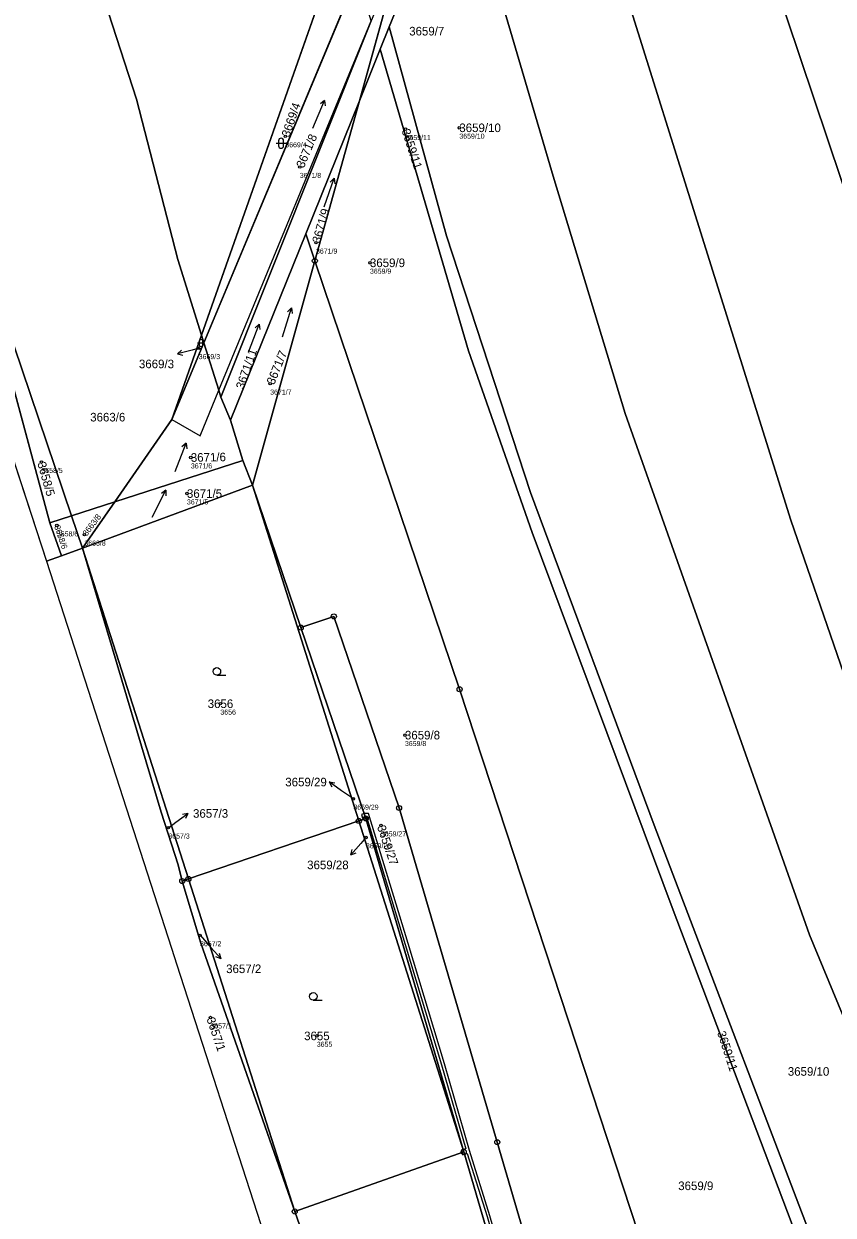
# Model space of a CAD drawing. Extents: x -761174 to -757114, y -1063806 to -1059397.
# Drawn here: x -760564.3 to -760404, y -1062680.5 to -1062444.5 of the extents above; entities that cross this region are included whole.
import ezdxf

# ---------------------------------------------------------------- set-up
doc = ezdxf.new("R2010")
doc.units = 0
for name, color, linetype in [('Definiční body', 7, 'Continuous'), ('Hranice parcel', 7, 'Continuous'), ('Parcelní čísla', 7, 'Continuous'), ('Polygon ku', 7, 'Continuous'), ('Polygon parcely', 7, 'Continuous'), ('Pop  PČ popisy', 7, 'Continuous'), ('Vnitřní kresba', 7, 'Continuous'), ('Věcná břemena k části', 7, 'Continuous'), ('Značky bodu BP', 7, 'Continuous'), ('Značky kultur', 7, 'Continuous')]:
    doc.layers.add(name, color=color, linetype=linetype)

msp = doc.modelspace()

# ---------------------------------------------------------------- linework, layer by layer
at = {"layer": 'Definiční body'}
for centre in [(-760512.49, -1062466.82), (-760488.67, -1062465.4), (-760478.03, -1062465.12), (-760509.62, -1062472.89), (-760506.41, -1062487.88), (-760495.73, -1062491.86), (-760529.63, -1062508.78), (-760515.48, -1062515.81), (-760531.19, -1062530.43), (-760560.78, -1062531.33), (-760531.96, -1062537.56), (-760557.71, -1062543.88), (-760552.27, -1062545.71), (-760525.34, -1062579.19), (-760488.8, -1062585.41), (-760499.01, -1062598.02), (-760535.64, -1062603.74), (-760493.55, -1062603.31), (-760496.52, -1062605.68), (-760529.37, -1062625.06), (-760527.31, -1062641.35), (-760506.25, -1062644.98)]:
    msp.add_circle(centre, 0.25, dxfattribs=at)
at = {"layer": 'Hranice parcel'}
for p, q in [((-760529.07, -1062506.18), (-760500.79, -1062425.75)), ((-760497.82, -1062459.77), (-760489.47, -1062429.76)), ((-760528.6, -1062507.69), (-760498.2, -1062434.94)), ((-760525.22, -1062518.46), (-760495.48, -1062443.91)), ((-760493.69, -1062449.54), (-760491.89, -1062445.1)), ((-760497.82, -1062459.77), (-760493.69, -1062449.54)), ((-760591.44, -1062454.1), (-760559.78, -1062550.95)), ((-760497.82, -1062459.77), (-760508.45, -1062486.1)), ((-760506.64, -1062491.46), (-760497.82, -1062459.77)), ((-760559.12, -1062543.33), (-760577.66, -1062474.56)), ((-760554.81, -1062541.95), (-760577.66, -1062474.56)), ((-760508.45, -1062486.1), (-760523.34, -1062523)), ((-760506.64, -1062491.46), (-760508.45, -1062486.1)), ((-760519.01, -1062535.92), (-760506.64, -1062491.46)), ((-760534.95, -1062522.89), (-760529.07, -1062506.18)), ((-760528.6, -1062507.69), (-760529.07, -1062506.18)), ((-760534.95, -1062522.89), (-760528.6, -1062507.69)), ((-760523.34, -1062523), (-760525.22, -1062518.46)), ((-760546.26, -1062539.2), (-760534.95, -1062522.89)), ((-760520.92, -1062531.04), (-760523.34, -1062523)), ((-760520.92, -1062531.04), (-760546.26, -1062539.2)), ((-760519.01, -1062535.92), (-760520.92, -1062531.04)), ((-760519.01, -1062535.92), (-760552.63, -1062548.39)), ((-760519.01, -1062535.92), (-760509.42, -1062564.12)), ((-760497.93, -1062602.4), (-760519.01, -1062535.92)), ((-760554.81, -1062541.95), (-760546.26, -1062539.2)), ((-760552.63, -1062548.39), (-760546.26, -1062539.2)), ((-760559.12, -1062543.33), (-760554.81, -1062541.95)), ((-760552.63, -1062548.39), (-760554.81, -1062541.95)), ((-760556.8, -1062549.88), (-760559.12, -1062543.33)), ((-760556.8, -1062549.88), (-760552.63, -1062548.39)), ((-760537.09, -1062600.69), (-760552.63, -1062548.39)), ((-760552.63, -1062548.39), (-760531.68, -1062613.9)), ((-760559.78, -1062550.95), (-760556.8, -1062549.88)), ((-760559.78, -1062550.95), (-760535.03, -1062627.6)), ((-760509.42, -1062564.12), (-760496.56, -1062601.93)), ((-760497.93, -1062602.4), (-760531.68, -1062613.9)), ((-760496.56, -1062601.93), (-760497.93, -1062602.4)), ((-760477.15, -1062667.96), (-760497.93, -1062602.4)), ((-760496.56, -1062601.93), (-760477.15, -1062667.96)), ((-760531.68, -1062613.9), (-760532.88, -1062614.31)), ((-760529.19, -1062626.62), (-760532.88, -1062614.31)), ((-760531.68, -1062613.9), (-760510.62, -1062679.76)), ((-760510.62, -1062679.76), (-760529.19, -1062626.62)), ((-760535.03, -1062627.6), (-760533.95, -1062630.93)), ((-760477.15, -1062667.96), (-760510.62, -1062679.76)), ((-760456.61, -1062738.15), (-760477.15, -1062667.96)), ((-760510.62, -1062679.76), (-760485.29, -1062752.31))]:
    msp.add_line(p, q, dxfattribs=at)
for points in [[(-760359.03, -1062598.65), (-760377.94, -1062548.27), (-760415.94, -1062435.02), (-760457.73, -1062294.15), (-760467.66, -1062267.71)], [(-760378.94, -1062635.52), (-760392.71, -1062599.89), (-760412.37, -1062542.84), (-760446.07, -1062435.29), (-760476.28, -1062329.05)], [(-760580.16, -1062341.72), (-760541.95, -1062459.45), (-760533.78, -1062491.19), (-760529.07, -1062506.18)], [(-760390.99, -1062667.67), (-760408.72, -1062624.98), (-760445.22, -1062521.7), (-760459.47, -1062474.68), (-760482.65, -1062395.66)], [(-760491.89, -1062445.1), (-760489.82, -1062439.96), (-760489.47, -1062429.76)], [(-760491.89, -1062445.1), (-760480.56, -1062486.5), (-760463.94, -1062537.36), (-760439.48, -1062603.21), (-760404.16, -1062695.94)], [(-760406.03, -1062698.38), (-760435.9, -1062619.55), (-760463.6, -1062545.28), (-760476.2, -1062509.31), (-760493.69, -1062449.54)], [(-760430.23, -1062721.73), (-760477.98, -1062576.32), (-760506.64, -1062491.46)], [(-760525.22, -1062518.46), (-760525.65, -1062517.09), (-760528.6, -1062507.69)], [(-760509.42, -1062564.12), (-760502.88, -1062561.89), (-760489.97, -1062599.84), (-760470.52, -1062666.02), (-760450.33, -1062735.04)], [(-760532.88, -1062614.31), (-760533.73, -1062611.1), (-760537.09, -1062600.69)], [(-760533.95, -1062630.93), (-760517.41, -1062682.16), (-760512.39, -1062694.98)]]:
    msp.add_lwpolyline(points, dxfattribs=at)
at = {"layer": 'Polygon ku'}
msp.add_lwpolyline([(-760641.69, -1062278.11), (-760615.05, -1062378.32), (-760614.77, -1062379.37), (-760614.04, -1062381.71), (-760591.44, -1062454.1), (-760559.78, -1062550.95), (-760535.03, -1062627.6), (-760533.95, -1062630.93), (-760517.41, -1062682.16), (-760512.39, -1062694.98), (-760503.17, -1062718.49), (-760492.21, -1062746.48), (-760517.18, -1062759.09), (-760525.26, -1062765.8), (-760535.26, -1062774.1), (-760557.5, -1062792.57), (-760589.26, -1062821.58), (-760637.28, -1062871.13)], dxfattribs=at)
at = {"layer": 'Polygon parcely'}
for points in [[(-760533.78, -1062491.19), (-760529.07, -1062506.18), (-760500.79, -1062425.75), (-760575.71, -1062179.08), (-760592.88, -1062117.85), (-760608.98, -1062059.6), (-760619.86, -1062023.13), (-760635.57, -1061977.23), (-760679.98, -1061865.8), (-760701.9, -1061821.27), (-760704.64, -1061824.79), (-760730.48, -1061860.52), (-760714.97, -1061897.09), (-760670.71, -1062020.74), (-760625.06, -1062187.5), (-760580.16, -1062341.72), (-760541.95, -1062459.45)], [(-760369.55, -1062448.69), (-760407.18, -1062305.67), (-760440.79, -1062189.54), (-760467.28, -1062265.76), (-760467.66, -1062267.71), (-760457.73, -1062294.15), (-760415.94, -1062435.02), (-760377.94, -1062548.27), (-760359.03, -1062598.65), (-760351.17, -1062587.7), (-760338.23, -1062572.36), (-760330.52, -1062565.65)], [(-760377.94, -1062548.27), (-760415.94, -1062435.02), (-760457.73, -1062294.15), (-760467.66, -1062267.71), (-760473.09, -1062295.7), (-760475.17, -1062317.47), (-760476.28, -1062329.05), (-760446.07, -1062435.29), (-760412.37, -1062542.84), (-760392.71, -1062599.89), (-760378.94, -1062635.52), (-760375.77, -1062627.04), (-760366.24, -1062608.68), (-760359.03, -1062598.65)], [(-760412.37, -1062542.84), (-760446.07, -1062435.29), (-760476.28, -1062329.05), (-760478.1, -1062348.09), (-760482.65, -1062395.66), (-760459.47, -1062474.68), (-760445.22, -1062521.7), (-760408.72, -1062624.98), (-760390.99, -1062667.67), (-760388.52, -1062661.21), (-760378.94, -1062635.52), (-760392.71, -1062599.89)], [(-760554.81, -1062541.95), (-760546.26, -1062539.2), (-760534.95, -1062522.89), (-760529.07, -1062506.18), (-760533.78, -1062491.19), (-760541.95, -1062459.45), (-760580.16, -1062341.72), (-760618.87, -1062350.37), (-760610.19, -1062377.86), (-760588.97, -1062441.1), (-760585.34, -1062441.77), (-760577.66, -1062474.56)], [(-760591.44, -1062454.1), (-760559.78, -1062550.95), (-760556.8, -1062549.88), (-760559.12, -1062543.33), (-760577.66, -1062474.56), (-760585.11, -1062452.59), (-760588.97, -1062441.1), (-760592.44, -1062440.45), (-760606.15, -1062400.62), (-760611.88, -1062381.5), (-760614.04, -1062381.71)], [(-760491.89, -1062445.1), (-760480.56, -1062486.5), (-760463.94, -1062537.36), (-760439.48, -1062603.21), (-760404.16, -1062695.94), (-760399.41, -1062689.74), (-760390.99, -1062667.67), (-760408.72, -1062624.98), (-760445.22, -1062521.7), (-760459.47, -1062474.68), (-760482.65, -1062395.66), (-760484.23, -1062412.14), (-760489.1, -1062428.43), (-760489.47, -1062429.76), (-760489.82, -1062439.96)], [(-760489.47, -1062429.76), (-760488.84, -1062411.43), (-760492.38, -1062420.57), (-760493.6, -1062439.33), (-760495.48, -1062443.91), (-760525.22, -1062518.46), (-760523.34, -1062523), (-760508.45, -1062486.1), (-760497.82, -1062459.77)], [(-760498.2, -1062434.94), (-760500.79, -1062425.75), (-760529.07, -1062506.18), (-760528.6, -1062507.69)], [(-760491.89, -1062445.1), (-760489.82, -1062439.96), (-760489.47, -1062429.76), (-760497.82, -1062459.77), (-760493.69, -1062449.54)], [(-760495.48, -1062443.91), (-760498.2, -1062434.94), (-760528.6, -1062507.69), (-760525.65, -1062517.09), (-760525.22, -1062518.46)], [(-760406.03, -1062698.38), (-760404.16, -1062695.94), (-760439.48, -1062603.21), (-760463.94, -1062537.36), (-760480.56, -1062486.5), (-760491.89, -1062445.1), (-760493.69, -1062449.54), (-760476.2, -1062509.31), (-760463.6, -1062545.28), (-760435.9, -1062619.55)], [(-760463.6, -1062545.28), (-760476.2, -1062509.31), (-760493.69, -1062449.54), (-760497.82, -1062459.77), (-760506.64, -1062491.46), (-760477.98, -1062576.32), (-760430.23, -1062721.73), (-760414.66, -1062709.65), (-760406.03, -1062698.38), (-760435.9, -1062619.55)], [(-760497.82, -1062459.77), (-760508.45, -1062486.1), (-760506.64, -1062491.46)], [(-760577.66, -1062474.56), (-760559.12, -1062543.33), (-760554.81, -1062541.95)], [(-760508.45, -1062486.1), (-760523.34, -1062523), (-760520.92, -1062531.04), (-760519.01, -1062535.92), (-760506.64, -1062491.46)], [(-760470.52, -1062666.02), (-760450.33, -1062735.04), (-760445.89, -1062732.85), (-760431.46, -1062722.68), (-760430.23, -1062721.73), (-760477.98, -1062576.32), (-760506.64, -1062491.46), (-760519.01, -1062535.92), (-760509.42, -1062564.12), (-760502.88, -1062561.89), (-760489.97, -1062599.84)], [(-760528.6, -1062507.69), (-760529.07, -1062506.18), (-760534.95, -1062522.89)], [(-760520.92, -1062531.04), (-760523.34, -1062523), (-760525.22, -1062518.46), (-760525.65, -1062517.09), (-760528.6, -1062507.69), (-760534.95, -1062522.89), (-760546.26, -1062539.2)], [(-760546.26, -1062539.2), (-760552.63, -1062548.39), (-760519.01, -1062535.92), (-760520.92, -1062531.04)], [(-760497.93, -1062602.4), (-760519.01, -1062535.92), (-760552.63, -1062548.39), (-760531.68, -1062613.9)], [(-760519.01, -1062535.92), (-760497.93, -1062602.4), (-760496.56, -1062601.93), (-760509.42, -1062564.12)], [(-760546.26, -1062539.2), (-760554.81, -1062541.95), (-760552.63, -1062548.39)], [(-760552.63, -1062548.39), (-760554.81, -1062541.95), (-760559.12, -1062543.33), (-760556.8, -1062549.88)], [(-760503.17, -1062718.49), (-760492.21, -1062746.48), (-760489.57, -1062753.22), (-760485.29, -1062752.31), (-760510.62, -1062679.76), (-760529.19, -1062626.62), (-760532.88, -1062614.31), (-760533.73, -1062611.1), (-760537.09, -1062600.69), (-760552.63, -1062548.39), (-760556.8, -1062549.88), (-760559.78, -1062550.95), (-760535.03, -1062627.6), (-760533.95, -1062630.93), (-760517.41, -1062682.16), (-760512.39, -1062694.98)], [(-760531.68, -1062613.9), (-760552.63, -1062548.39), (-760537.09, -1062600.69), (-760533.73, -1062611.1), (-760532.88, -1062614.31)], [(-760477.15, -1062667.96), (-760456.61, -1062738.15), (-760450.33, -1062735.04), (-760470.52, -1062666.02), (-760489.97, -1062599.84), (-760502.88, -1062561.89), (-760509.42, -1062564.12), (-760496.56, -1062601.93)], [(-760497.93, -1062602.4), (-760531.68, -1062613.9), (-760510.62, -1062679.76), (-760477.15, -1062667.96)], [(-760496.56, -1062601.93), (-760497.93, -1062602.4), (-760477.15, -1062667.96)], [(-760531.68, -1062613.9), (-760532.88, -1062614.31), (-760529.19, -1062626.62), (-760510.62, -1062679.76)], [(-760477.15, -1062667.96), (-760510.62, -1062679.76), (-760485.29, -1062752.31), (-760456.61, -1062738.15)]]:
    msp.add_lwpolyline(points, close=True, dxfattribs=at)
at = {"layer": 'Pop  PČ popisy'}
for p, q in [((-760530.96, -1062509.14), (-760533.86, -1062509.92)), ((-760533.86, -1062509.92), (-760533.02, -1062509.17)), ((-760529.63, -1062508.78), (-760530.96, -1062509.14)), ((-760533.86, -1062509.92), (-760532.76, -1062510.14)), ((-760501.34, -1062596.41), (-760503.8, -1062594.69)), ((-760503.8, -1062594.69), (-760502.69, -1062594.85)), ((-760503.8, -1062594.69), (-760503.27, -1062595.67)), ((-760499.01, -1062598.02), (-760501.34, -1062596.41)), ((-760534.19, -1062602.68), (-760531.76, -1062600.92)), ((-760531.76, -1062600.92), (-760532.87, -1062601.1)), ((-760531.76, -1062600.92), (-760532.28, -1062601.91)), ((-760535.64, -1062603.74), (-760534.19, -1062602.68)), ((-760496.52, -1062605.68), (-760497.53, -1062606.85)), ((-760497.53, -1062606.85), (-760499.5, -1062609.11)), ((-760499.5, -1062609.11), (-760499.22, -1062608.03)), ((-760499.5, -1062609.11), (-760498.46, -1062608.69)), ((-760529.37, -1062625.06), (-760527.2, -1062627.48)), ((-760527.2, -1062627.48), (-760525.19, -1062629.71)), ((-760525.19, -1062629.71), (-760526.23, -1062629.3)), ((-760525.19, -1062629.71), (-760525.49, -1062628.63))]:
    msp.add_line(p, q, dxfattribs=at)
at = {"layer": 'Vnitřní kresba'}
for p, q in [((-760525.65, -1062517.09), (-760495.48, -1062443.91)), ((-760529.37, -1062526.11), (-760525.65, -1062517.09)), ((-760534.95, -1062522.89), (-760529.37, -1062526.11))]:
    msp.add_line(p, q, dxfattribs=at)
at = {"layer": 'Věcná břemena k části'}
for points in [[(-760496.66, -1062601.65), (-760496.89, -1062600.95), (-760497.37, -1062601.11), (-760497.19, -1062601.83)], [(-760488.19, -1062626.69), (-760496.02, -1062600.9), (-760496.89, -1062600.95), (-760496.66, -1062601.65), (-760496.44, -1062601.6), (-760488.77, -1062626.87), (-760481.57, -1062650.69), (-760476.75, -1062667.33), (-760477.29, -1062667.5), (-760477.02, -1062668.41), (-760476.48, -1062668.24), (-760472.54, -1062680.78), (-760461.82, -1062717.95), (-760455.93, -1062737.81), (-760455.38, -1062737.54), (-760461.24, -1062717.79), (-760471.96, -1062680.6), (-760476.03, -1062667.65), (-760480.99, -1062650.51)], [(-760477.5, -1062668.08), (-760477.15, -1062667.96), (-760477.29, -1062667.5), (-760477.3, -1062667.5), (-760477.64, -1062667.6)], [(-760477.5, -1062668.08), (-760477.37, -1062668.52), (-760477.02, -1062668.41), (-760477.15, -1062667.96)]]:
    msp.add_lwpolyline(points, close=True, dxfattribs=at)
at = {"layer": 'Značky bodu BP'}
for centre, radius in [((-760506.64, -1062491.46), 0.5), ((-760506.64, -1062491.46), 0.0303), ((-760502.88, -1062561.89), 0.5), ((-760509.42, -1062564.12), 0.5), ((-760502.88, -1062561.89), 0.0303), ((-760509.42, -1062564.12), 0.0303), ((-760477.98, -1062576.32), 0.5), ((-760477.98, -1062576.32), 0.0303), ((-760496.56, -1062601.93), 0.5), ((-760489.97, -1062599.84), 0.5), ((-760489.97, -1062599.84), 0.0303), ((-760497.93, -1062602.4), 0.5), ((-760497.93, -1062602.4), 0.0303), ((-760496.56, -1062601.93), 0.0303), ((-760532.88, -1062614.31), 0.5), ((-760532.88, -1062614.31), 0.0303), ((-760531.68, -1062613.9), 0.5), ((-760531.68, -1062613.9), 0.0303), ((-760477.15, -1062667.96), 0.5), ((-760470.52, -1062666.02), 0.5), ((-760470.52, -1062666.02), 0.0303), ((-760477.15, -1062667.96), 0.0303), ((-760510.62, -1062679.76), 0.5), ((-760510.62, -1062679.76), 0.0303)]:
    msp.add_circle(centre, radius, dxfattribs=at)
at = {"layer": 'Značky kultur'}
for p, q in [((-760507.05, -1062465.22), (-760504.7, -1062459.7)), ((-760504.7, -1062459.7), (-760505.55, -1062460.4)), ((-760504.7, -1062459.7), (-760504.62, -1062460.79)), ((-760514.32, -1062468.18), (-760512.32, -1062468.18)), ((-760513.82, -1062467.68), (-760513.82, -1062468.68)), ((-760512.82, -1062468.68), (-760512.82, -1062467.68)), ((-760504.79, -1062480.79), (-760502.84, -1062475.12)), ((-760502.84, -1062475.12), (-760503.63, -1062475.88)), ((-760502.84, -1062475.12), (-760502.68, -1062476.21)), ((-760513.04, -1062506.52), (-760511.29, -1062500.79)), ((-760511.29, -1062500.79), (-760512.06, -1062501.57)), ((-760511.29, -1062500.79), (-760511.1, -1062501.87)), ((-760519.8, -1062509.58), (-760517.65, -1062503.98)), ((-760517.65, -1062503.98), (-760518.47, -1062504.71)), ((-760517.65, -1062503.98), (-760517.53, -1062505.07)), ((-760529.89, -1062507.74), (-760528.49, -1062507.74)), ((-760529.54, -1062507.39), (-760529.54, -1062508.09)), ((-760528.84, -1062508.09), (-760528.84, -1062507.39)), ((-760534.28, -1062533.21), (-760532.13, -1062527.61)), ((-760532.13, -1062527.61), (-760532.95, -1062528.34)), ((-760532.13, -1062527.61), (-760532.01, -1062528.7)), ((-760538.85, -1062542.26), (-760536.12, -1062536.92)), ((-760536.12, -1062536.92), (-760537.01, -1062537.56)), ((-760536.12, -1062536.92), (-760536.12, -1062538.01)), ((-760526.04, -1062573.53), (-760524.29, -1062573.53)), ((-760506.95, -1062637.91), (-760505.2, -1062637.91))]:
    msp.add_line(p, q, dxfattribs=at)
for centre in [(-760526.04, -1062572.78), (-760506.95, -1062637.16)]:
    msp.add_circle(centre, 0.75, dxfattribs=at)
for centre, radius, start, end in [((-760513.32, -1062467.68), 0.5, 0, 180), ((-760513.32, -1062468.68), 0.5, 180, 359.9879), ((-760529.19, -1062507.39), 0.35, 0, 180), ((-760529.19, -1062508.09), 0.35, 180, 359.9879)]:
    msp.add_arc(centre, radius, start, end, dxfattribs=at)

# ---------------------------------------------------------------- texts
at = {"layer": 'Definiční body'}
for s, p in [('3659/11', (-760488.67, -1062467.56)), ('3659/10', (-760478.03, -1062467.28)), ('3669/4', (-760512.49, -1062468.98)), ('3671/8', (-760509.62, -1062475.05)), ('3671/9', (-760506.41, -1062490.04)), ('3659/9', (-760495.73, -1062494.02)), ('3669/3', (-760529.63, -1062510.94)), ('3671/7', (-760515.48, -1062517.97)), ('3658/5', (-760560.78, -1062533.49)), ('3671/6', (-760531.19, -1062532.59)), ('3671/5', (-760531.96, -1062539.72)), ('3658/6', (-760557.71, -1062546.04)), ('3663/8', (-760552.27, -1062547.87)), ('3656', (-760525.34, -1062581.35)), ('3659/8', (-760488.8, -1062587.57)), ('3659/29', (-760499.01, -1062600.18)), ('3657/3', (-760535.64, -1062605.9)), ('3659/27', (-760493.55, -1062605.47)), ('3659/28', (-760496.52, -1062607.84)), ('3657/2', (-760529.37, -1062627.22)), ('3657/1', (-760527.31, -1062643.51)), ('3655', (-760506.25, -1062647.14))]:
    msp.add_text(s, height=1, dxfattribs=at).set_placement(p)
at = {"layer": 'Parcelní čísla'}
for s, p in [('3659/7', (-760487.96, -1062446.83)), ('3659/10', (-760478.03, -1062465.97)), ('3659/9', (-760495.73, -1062492.71)), ('3669/3', (-760541.47, -1062512.74)), ('3663/6', (-760551.12, -1062523.28)), ('3671/5', (-760531.96, -1062538.41)), ('3656', (-760527.85, -1062580.04)), ('3659/8', (-760488.8, -1062586.26)), ('3659/29', (-760512.49, -1062595.55)), ('3657/3', (-760530.76, -1062601.77)), ('3659/28', (-760508.16, -1062611.96)), ('3657/2', (-760524.2, -1062632.54)), ('3655', (-760508.76, -1062645.83)), ('3659/10', (-760412.99, -1062652.87)), ('3659/9', (-760434.69, -1062675.52))]:
    msp.add_text(s, height=1.7, dxfattribs=at).set_placement(p)
for s, height, rotation, p in [('3669/4', 1.7, 71, (-760511.69, -1062467.1)), ('3671/8', 1.7, 67, (-760508.84, -1062473.22)), ('3659/11', 1.7, 288, (-760489.48, -1062465.66)), ('3671/9', 1.7, 74, (-760505.59, -1062488.11)), ('3671/11', 1.7, 71, (-760520.73, -1062517.03)), ('3671/7', 1.7, 68, (-760514.69, -1062516.13)), ('3671/6', 1.7, 1, (-760531.18, -1062531.28)), ('3658/5', 1.7, 286, (-760561.6, -1062531.56)), ('3663/8', 1.19, 53, (-760551.79, -1062546.07)), ('3658/6', 1.19, 289, (-760558.27, -1062544.07)), ('3659/27', 1.7, 289, (-760494.35, -1062603.59)), ('3657/1', 1.7, 289, (-760528.11, -1062641.63)), ('3659/11', 1.7, 288, (-760427, -1062644.33))]:
    msp.add_text(s, height=height, rotation=rotation, dxfattribs=at).set_placement(p)

doc.saveas('drawing.dxf')
